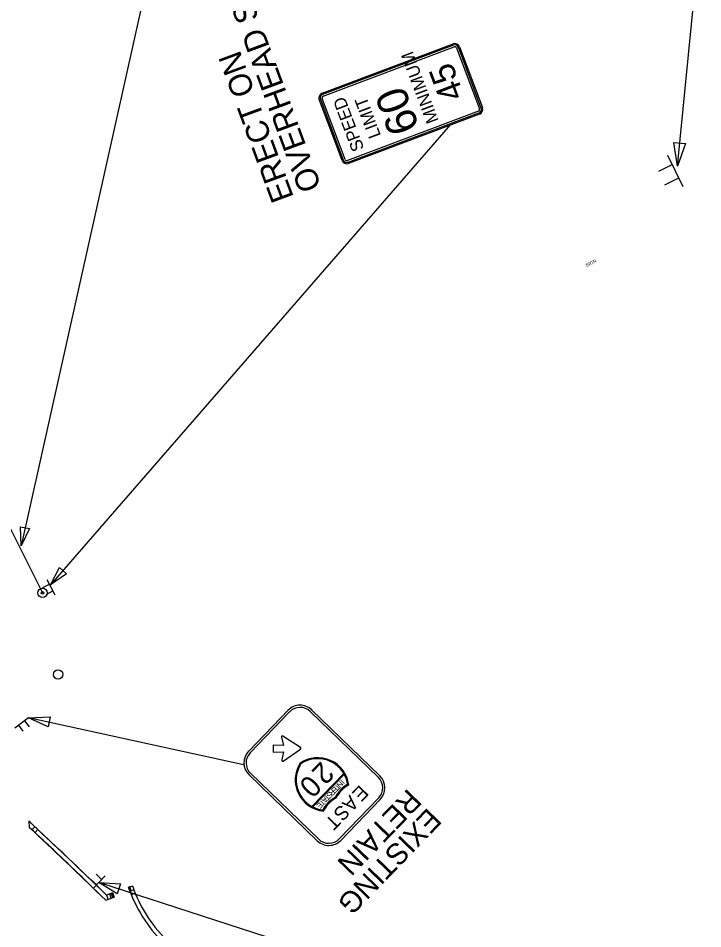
# Model space of a CAD drawing. Extents: x -5665 to 1997148, y 4 to 812485.
# Drawn here: x 1971841 to 1972650, y 802384 to 803460 of the extents above; entities that cross this region are included whole.
import ezdxf

# ---------------------------------------------------------------- set-up
doc = ezdxf.new("R2010")
doc.units = 0
for name, color, linetype in [('Default', 7, 'Continuous'), ('RD_EX_Misc', 7, 'Continuous'), ('RD_PD_Final_TX', 7, 'Continuous'), ('RD_PD_SW', 7, 'Continuous'), ('RD_SHT_TX', 7, 'Continuous'), ('RD_Sketch10', 7, 'Continuous')]:
    doc.layers.add(name, color=color, linetype=linetype)

msp = doc.modelspace()

# ---------------------------------------------------------------- linework, layer by layer
at = {"layer": 'RD_EX_Misc'}
for p, q in [((1972200.4, 803371.2), (1972355.1, 803429.5)), ((1972362.7, 803426), (1972389.8, 803354.2)), ((1972210.5, 803327.6), (1972197, 803363.6)), ((1972386.4, 803346.6), (1972231.6, 803288.3)), ((1972224, 803291.7), (1972210.5, 803327.6)), ((1972107.4, 802577.2), (1971853.5, 802633)), ((1972235.5, 802341.4), (1971936.5, 802438.4))]:
    msp.add_line(p, q, dxfattribs=at)
for points in [[(1972355.7, 803428.1), (1972200.9, 803369.8)], [(1972201.7, 803367.7), (1972356.4, 803426)], [(1972359.3, 803424.7), (1972386.4, 803352.9)], [(1972388.4, 803353.7), (1972361.4, 803425.5)], [(1972198.3, 803364.1), (1972225.4, 803292.2)], [(1972227.5, 803293), (1972200.4, 803364.9)], [(1972385.1, 803350), (1972230.3, 803291.7)], [(1972231.1, 803289.7), (1972385.8, 803348)]]:
    msp.add_lwpolyline(points, dxfattribs=at)
for centre, radius, start, end in [((1972357.2, 803423.9), 5.91, 20.6458, 110.6458), ((1972357.2, 803423.9), 4.43, 20.6458, 110.6458), ((1972357.2, 803423.9), 2.21, 20.6458, 110.6458), ((1972202.5, 803365.6), 5.91, 110.6458, 200.6458), ((1972202.5, 803365.6), 4.43, 110.6458, 200.6458), ((1972202.5, 803365.6), 2.21, 110.6458, 200.6458), ((1972384.3, 803352.1), 2.21, 290.6458, 20.6458), ((1972384.3, 803352.1), 4.43, 290.6458, 20.6458), ((1972384.3, 803352.1), 5.91, 290.6458, 20.6458), ((1972229.5, 803293.8), 5.91, 200.6458, 290.6458), ((1972229.5, 803293.8), 4.43, 200.6458, 290.6458), ((1972229.5, 803293.8), 2.21, 200.6458, 290.6458)]:
    msp.add_arc(centre, radius, start, end, dxfattribs=at)
at = {"layer": 'RD_PD_Final_TX'}
for points in [[(1972616.2, 803313.1), (1972629.8, 803311.7), (1972620.3, 803284.9)], [(1971843.8, 802858.8), (1971854.6, 802856.6), (1971844.6, 802836.1)], [(1971889.8, 802810.5), (1971898.1, 802803.3), (1971879.5, 802790.3)], [(1971879.1, 802634.3), (1971876.7, 802622.2), (1971853.5, 802633)], [(1971962, 802436.6), (1971958.2, 802424.8), (1971936.5, 802438.4)]]:
    msp.add_lwpolyline(points, close=True, dxfattribs=at)
at = {"layer": 'RD_PD_SW'}
for p, q in [((1971853.8, 802510.8), (1971854.3, 802503.5)), ((1971853.8, 802510.8), (1971854.3, 802503.5)), ((1971857.4, 802500.6), (1971860.8, 802504.2)), ((1971860.8, 802504.2), (1971857.4, 802500.6)), ((1971857.4, 802500.6), (1971860.8, 802504.2)), ((1971864.5, 802500.8), (1971861.1, 802497.2)), ((1971861.1, 802497.2), (1971864.5, 802500.8)), ((1971861.1, 802497.2), (1971864.5, 802500.8)), ((1971951.2, 802419.6), (1971949.3, 802424.8)), ((1971976.2, 802434.1), (1971970.7, 802432.2)), ((1971977.9, 802429.6), (1971973.2, 802427.8)), ((1971979.4, 802425.7), (1971974.9, 802423.8)), ((1971944.7, 802417.3), (1971954.7, 802420.8)), ((1971944.7, 802417.3), (1971954.7, 802420.8)), ((1971945.6, 802423.4), (1971947.4, 802418.3))]:
    msp.add_line(p, q, dxfattribs=at)
for points in [[(1971861.1, 802497.2), (1971861.1, 802497.2)], [(1971952.8, 802426), (1971950.7, 802425.2), (1971945.6, 802423.4)], [(1971952.8, 802426), (1971950.7, 802425.2), (1971945.6, 802423.4)], [(1971976.2, 802434.1), (1971975, 802433.7), (1971971.5, 802432.5)]]:
    msp.add_lwpolyline(points, dxfattribs=at)
for points in [[(1971954.4, 802421), (1971952.7, 802425.7), (1971951.2, 802425.2), (1971952.9, 802420.5)], [(1971974.7, 802428.3), (1971973, 802433), (1971971.5, 802432.4), (1971973.2, 802427.7)]]:
    msp.add_lwpolyline(points, close=True, dxfattribs=at)
for centre, radius in [((1971951.6, 802425), 0.146), ((1971951.6, 802425), 0.073), ((1971951.7, 802424.6), 0.073), ((1971951.7, 802424.6), 0.146), ((1971951.9, 802424.2), 0.146), ((1971951.9, 802424.2), 0.073), ((1971952, 802423.9), 0.146), ((1971952, 802425.2), 0.146), ((1971952, 802423.9), 0.073), ((1971952, 802425.2), 0.073), ((1971952.2, 802424.8), 0.146), ((1971952.1, 802423.5), 0.146), ((1971952.2, 802424.8), 0.073), ((1971952.3, 802424.4), 0.146), ((1971952.3, 802424.4), 0.073), ((1971952.5, 802424), 0.146), ((1971952.5, 802425.3), 0.146), ((1971952.5, 802424), 0.073), ((1971952.5, 802425.3), 0.073), ((1971952.7, 802425), 0.146), ((1971952.6, 802423.7), 0.146), ((1971952.6, 802423.7), 0.073), ((1971952.7, 802425), 0.073), ((1971952.8, 802424.6), 0.073), ((1971952.8, 802424.6), 0.146), ((1971952.9, 802424.2), 0.146), ((1971952.9, 802424.2), 0.073), ((1971953.1, 802423.8), 0.146), ((1971953.1, 802423.8), 0.073), ((1971953.2, 802423.5), 0.146), ((1971971.9, 802432.2), 0.146), ((1971971.9, 802432.2), 0.073), ((1971972, 802431.8), 0.146), ((1971972, 802431.8), 0.073), ((1971972.1, 802431.5), 0.146), ((1971972.1, 802431.5), 0.073), ((1971972.3, 802431.1), 0.146), ((1971972.3, 802432.4), 0.146), ((1971972.3, 802431.1), 0.073), ((1971972.3, 802432.4), 0.073), ((1971972.5, 802432), 0.146), ((1971972.4, 802430.7), 0.146), ((1971972.5, 802432), 0.073), ((1971972.4, 802430.7), 0.073), ((1971972.6, 802430.3), 0.146), ((1971972.6, 802431.6), 0.146), ((1971972.6, 802431.6), 0.073), ((1971972.6, 802430.3), 0.073), ((1971972.8, 802431.3), 0.146), ((1971972.7, 802430), 0.146), ((1971972.7, 802430), 0.073), ((1971972.8, 802432.6), 0.146), ((1971972.8, 802432.6), 0.073), ((1971972.8, 802431.3), 0.073), ((1971972.9, 802430.9), 0.146), ((1971972.8, 802429.6), 0.146), ((1971973, 802432.2), 0.146), ((1971972.9, 802430.9), 0.073), ((1971972.8, 802429.6), 0.073), ((1971973, 802429.2), 0.146), ((1971973, 802432.2), 0.073), ((1971973.1, 802431.8), 0.146), ((1971973, 802430.5), 0.146), ((1971973, 802429.2), 0.073), ((1971973.1, 802431.8), 0.073), ((1971973, 802430.5), 0.073), ((1971973.2, 802430.1), 0.146), ((1971973.1, 802428.8), 0.146), ((1971973.1, 802428.8), 0.073), ((1971973.2, 802431.4), 0.146), ((1971973.2, 802430.1), 0.073), ((1971973.3, 802428.5), 0.146), ((1971973.2, 802431.4), 0.073), ((1971973.4, 802431.1), 0.146), ((1971973.3, 802429.8), 0.146), ((1971973.3, 802429.8), 0.073), ((1971973.3, 802428.5), 0.073), ((1971973.4, 802431.1), 0.073), ((1971973.4, 802429.4), 0.146), ((1971973.4, 802428.1), 0.073), ((1971973.4, 802428.1), 0.146), ((1971973.5, 802430.7), 0.073), ((1971973.5, 802430.7), 0.146), ((1971973.4, 802429.4), 0.073), ((1971973.6, 802429), 0.146), ((1971973.6, 802430.3), 0.146), ((1971973.6, 802429), 0.073), ((1971973.6, 802430.3), 0.073), ((1971973.8, 802429.9), 0.146), ((1971973.7, 802428.6), 0.146), ((1971973.8, 802429.9), 0.073), ((1971973.7, 802428.6), 0.073), ((1971973.9, 802428.3), 0.146), ((1971973.9, 802429.6), 0.146), ((1971973.9, 802428.3), 0.073), ((1971973.9, 802429.6), 0.073), ((1971974.1, 802429.2), 0.146), ((1971974.1, 802429.2), 0.073), ((1971974.2, 802428.8), 0.146), ((1971974.2, 802428.8), 0.073), ((1971974.3, 802428.4), 0.146), ((1971974.3, 802428.4), 0.073), ((1971952.1, 802423.5), 0.073), ((1971952.3, 802423.1), 0.146), ((1971952.3, 802423.1), 0.073), ((1971952.4, 802422.7), 0.146), ((1971952.4, 802422.7), 0.073), ((1971952.6, 802422.4), 0.146), ((1971952.6, 802422.4), 0.073), ((1971952.7, 802422), 0.146), ((1971952.7, 802423.3), 0.146), ((1971952.7, 802422), 0.073), ((1971952.7, 802423.3), 0.073), ((1971952.9, 802422.9), 0.146), ((1971952.8, 802421.6), 0.146), ((1971952.9, 802422.9), 0.073), ((1971952.8, 802421.6), 0.073), ((1971953, 802421.2), 0.146), ((1971953, 802422.5), 0.146), ((1971953, 802422.5), 0.073), ((1971953, 802421.2), 0.073), ((1971953.2, 802422.2), 0.146), ((1971953.1, 802420.9), 0.146), ((1971953.1, 802420.9), 0.073), ((1971953.2, 802423.5), 0.073), ((1971953.2, 802422.2), 0.073), ((1971953.4, 802423.1), 0.146), ((1971953.3, 802421.8), 0.146), ((1971953.3, 802421.8), 0.073), ((1971953.4, 802423.1), 0.073), ((1971953.4, 802421.4), 0.146), ((1971953.5, 802422.7), 0.073), ((1971953.5, 802422.7), 0.146), ((1971953.4, 802421.4), 0.073), ((1971953.6, 802421), 0.146), ((1971953.6, 802422.3), 0.146), ((1971953.6, 802421), 0.073), ((1971953.6, 802422.3), 0.073), ((1971953.8, 802422), 0.146), ((1971953.8, 802422), 0.073), ((1971953.9, 802421.6), 0.073), ((1971953.9, 802421.6), 0.146), ((1971954.1, 802421.2), 0.146), ((1971954.1, 802421.2), 0.073)]:
    msp.add_circle(centre, radius, dxfattribs=at)
for centre, radius, start, end in [((1967911.4, 798277.1), 5785, 46.94513, 47.04036), ((1967911.4, 798277.1), 5785, 45.7854, 47.04036), ((1967911.4, 798277.1), 5780, 46.94513, 46.98797), ((1967911.4, 798277.1), 5780, 45.74921, 46.98797), ((1967911.4, 798277.1), 5780, 46.89556, 46.94513), ((1967911.4, 798277.1), 5785, 46.89561, 46.94513), ((1967911.4, 798277.1), 5785, 45.7854, 46.89561), ((1967911.4, 798277.1), 5780, 45.74921, 46.89556), ((1972136, 802490.5), 194.2, 199.3907, 201.0273), ((1972136, 802490.5), 194.2, 199.3907, 201.0273), ((1972134.8, 802489.6), 173, 199.268, 224.8091), ((1972134.8, 802489.6), 173, 199.268, 224.8091), ((1972134.8, 802489.6), 168, 199.268, 224.8091), ((1972134.8, 802489.6), 168, 199.268, 224.8091)]:
    msp.add_arc(centre, radius, start, end, dxfattribs=at)
at = {"layer": 'RD_SHT_TX'}
for p, q in [((1972165.8, 804274.7), (1971844.6, 802836.1)), ((1972620.3, 803284.9), (1972650.3, 803586.7)), ((1972352, 803334.2), (1971879.5, 802790.3)), ((1972627.1, 803260.6), (1972609, 803297.5)), ((1972598.3, 803278.9), (1972614.3, 803286.8)), ((1972605.4, 803262.8), (1972621.4, 803270.7)), ((1971820.9, 802878.5), (1971870, 802780.6)), ((1971870.2, 802786.8), (1971878.1, 802790.9)), ((1971884.9, 802778), (1971875.4, 802796.2)), ((1971874.1, 802778.8), (1971881.9, 802783)), ((1972113.6, 802593.4), (1972160.2, 802641.8)), ((1972162, 802640.1), (1972115.4, 802591.7)), ((1972162, 802640.1), (1972162, 802640.1)), ((1972266.9, 802562.5), (1972186.4, 802640.5)), ((1972187.8, 802642.5), (1972268.6, 802564.3)), ((1971853.5, 802633), (1971837, 802620.9)), ((1971854.4, 802622.2), (1971849.1, 802629.4)), ((1971847.1, 802617.2), (1971841.8, 802624.4)), ((1972151.9, 802623.1), (1972151.9, 802623.1)), ((1972152.2, 802610), (1972154.8, 802600.3)), ((1972174.8, 802597.9), (1972154, 802611.3)), ((1972154.8, 802600.3), (1972142.5, 802600.6)), ((1972142.5, 802600.6), (1972142.6, 802592.2)), ((1972154.5, 802581.8), (1972174.8, 802595.9)), ((1972142.6, 802592.2), (1972154.9, 802592.9)), ((1972142.6, 802592.2), (1972142.6, 802592.2)), ((1972154.9, 802592.9), (1972152.6, 802583.1)), ((1972174.4, 802579.3), (1972175.1, 802578.3)), ((1972175.5, 802578.6), (1972174.4, 802579.3)), ((1972194.6, 802487.6), (1972114, 802565.6)), ((1972115.8, 802567.4), (1972196.3, 802489.4)), ((1972115.8, 802567.4), (1972115.8, 802567.4)), ((1972225.9, 802567.1), (1972188.3, 802528.2)), ((1972225.9, 802567.1), (1972188.3, 802528.2)), ((1972189.2, 802527.4), (1972226.8, 802566.2)), ((1972189.5, 802527.6), (1972226.6, 802566)), ((1972226.8, 802566.2), (1972225.9, 802567.1)), ((1972225.9, 802567.1), (1972225.9, 802567.1)), ((1972230.6, 802553.6), (1972231.9, 802553.7)), ((1972231.9, 802553.7), (1972231.3, 802554.8)), ((1972266.9, 802562.5), (1972266.9, 802562.5)), ((1972215.8, 802538.8), (1972216.9, 802538.2)), ((1972216.9, 802538.2), (1972216.3, 802539.3)), ((1972220.6, 802489.8), (1972267.3, 802538.2)), ((1972269.1, 802536.5), (1972222.4, 802488.1)), ((1972188.3, 802528.2), (1972189.2, 802527.4)), ((1972200.8, 802523.3), (1972201.9, 802522.7)), ((1972201.9, 802522.7), (1972202, 802524)), ((1972220.6, 802489.8), (1972220.6, 802489.8)), ((1971929.9, 802431.3), (1971943.9, 802446.3)), ((1971933.3, 802448.1), (1971939.8, 802442)), ((1971927.1, 802441.8), (1971933.6, 802435.8))]:
    msp.add_line(p, q, dxfattribs=at)
msp.add_lwpolyline([(1972174.8, 802595.9), (1972174.8, 802597.9)], dxfattribs=at)
for centre in [(1971869.9, 802780.6), (1971888.3, 802684.3)]:
    msp.add_circle(centre, 5.54, dxfattribs=at)
for centre, radius, start, end in [((1972174.4, 802628.4), 19.5, 45.3406, 136.5338), ((1972174.4, 802628.1), 17.2, 45.9372, 135.9372), ((1972153.4, 802610.3), 1.23, 57.1151, 194.8993), ((1972174.1, 802596.9), 1.23, 304.7593, 57.1151), ((1972127.7, 802579.7), 19.7, 135.9372, 225.9372), ((1972127.7, 802579.7), 17.2, 135.9372, 225.9372), ((1972195.3, 802548.9), 36.9, 7.6061, 124.4002), ((1972153.8, 802582.8), 1.23, 166.9751, 304.7593), ((1972205.5, 802559.5), 36.9, 147.4741, 264.2682), ((1972205.5, 802559.5), 35.7, 147.8666, 241.1839), ((1972195.3, 802548.9), 35.7, 30.6904, 124.0077), ((1972195.3, 802548.9), 35.7, 8.933, 28.6739), ((1972254.9, 802550.2), 19.7, 315.9372, 45.9372), ((1972249.7, 802521.4), 38.1, 118.9463, 152.9281), ((1972249.8, 802521.5), 38.1, 120.3765, 152.5117), ((1972249.7, 802521.4), 36.9, 118.9463, 152.9281), ((1972254.9, 802550.2), 17.2, 315.9372, 45.9372), ((1972234.7, 802505.9), 38.1, 118.9463, 152.9281), ((1972234.7, 802505.9), 38.1, 119.3627, 151.4979), ((1972234.7, 802505.9), 36.9, 118.9463, 152.9281), ((1972205.5, 802559.5), 35.7, 243.2005, 262.9413), ((1972208.3, 802501.8), 17.2, 225.9372, 315.9372), ((1972208.3, 802501.8), 19.7, 225.9372, 315.9372)]:
    msp.add_arc(centre, radius, start, end, dxfattribs=at)
at = {"layer": 'RD_Sketch10'}
msp.add_circle((1971869.9, 802780.6), 1.5, dxfattribs=at)

# ---------------------------------------------------------------- texts
at = {"layer": 'Default'}
msp.add_text('SIGN', height=4, rotation=28.0139, dxfattribs=at).set_placement((1972513.1, 803165.6))
at = {"layer": 'RD_EX_Misc'}
for s, height, rotation, p in [('OVERHEAD SUPPORT', 27, 110.2575, (1972199.9, 803260.4)), ('ERECT ON', 27, 110.2575, (1972167.2, 803248.3)), ('MINIMUM', 14.76, 110.6458, (1972338.4, 803338.8)), ('45', 29.53, 110.6458, (1972368.7, 803368.3)), ('60', 36.91, 110.6458, (1972315.9, 803330.5)), ('SPEED', 14.76, 110.6458, (1972250.3, 803305.7)), ('LIMIT', 14.76, 110.6458, (1972270.1, 803321.2))]:
    msp.add_text(s, height=height, rotation=rotation, dxfattribs=at).set_placement(p)
at = {"layer": 'RD_SHT_TX'}
for s, height, rotation, p in [('2', 24.6, 225.9372, (1972199.2, 802582.5)), ('0', 24.6, 225.9372, (1972184.2, 802567)), ('T', 6.56, 225.9372, (1972218.1, 802555.4)), ('N', 6.56, 225.9372, (1972221.3, 802558.7)), ('I', 6.56, 225.9372, (1972222.9, 802560.4)), ('E', 16.4, 225.9372, (1972244.9, 802554.5)), ('S', 6.56, 225.9372, (1972208.9, 802546)), ('R', 6.56, 225.9372, (1972212, 802549.2)), ('E', 6.56, 225.9372, (1972215.1, 802552.4)), ('RETAIN', 25, 226.0326, (1972301.9, 802550.3)), ('A', 16.4, 225.9372, (1972233.2, 802542.4)), ('E', 6.56, 225.9372, (1972197.2, 802533.8)), ('T', 6.56, 225.9372, (1972200.2, 802536.9)), ('A', 6.56, 225.9372, (1972203.4, 802540.2)), ('T', 6.56, 225.9372, (1972206, 802542.9)), ('S', 16.4, 225.9372, (1972222.7, 802531.5)), ('EXISTING', 25, 226.0326, (1972325.4, 802527.7)), ('T', 16.4, 225.9372, (1972211.8, 802520.2))]:
    msp.add_text(s, height=height, rotation=rotation, dxfattribs=at).set_placement(p)

doc.saveas('drawing.dxf')
